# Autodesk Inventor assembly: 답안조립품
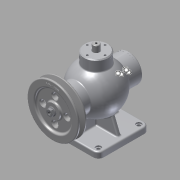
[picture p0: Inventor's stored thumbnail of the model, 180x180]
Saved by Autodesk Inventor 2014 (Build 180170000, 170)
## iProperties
Created: 2015-10
Part Number: 답안조립품
Document SubType Name: Assembly
Designer: youjin03
Author: youjin03
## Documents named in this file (19)
- C:\Users\youjin03\Desktop\451010V1015\답안조립품.iam
- C:\Users\youjin03\Desktop\451010V1015\본체.ipt
- C:\Users\youjin03\Desktop\451010V1015\뒤커버.ipt
- C:\Users\youjin03\Desktop\451010V1015\앞커버.ipt
- C:\Users\youjin03\Desktop\451010V1015\상부커버.ipt
- C:\Users\youjin03\Desktop\451010V1015\볼트 M4 x 16.ipt
- C:\Users\youjin03\Desktop\451010V1015\볼트 M 4 x 12.ipt
- C:\Users\youjin03\Desktop\451010V1015\오일실 15 30 7.ipt
- C:\Users\youjin03\Desktop\451010V1015\편심축.ipt
- C:\Users\youjin03\Desktop\451010V1015\베어링- 6202.ipt
- KS B 2023 - 6202 - 15 x 35 x 11 - 7.8.ipt
- C:\Users\youjin03\Desktop\451010V1015\부시.ipt
- C:\Users\youjin03\Desktop\451010V1015\키 4 x 4 x 12.ipt
- C:\Users\youjin03\Desktop\451010V1015\V-벨트풀리.ipt
- C:\Users\youjin03\Desktop\451010V1015\너트 M8.ipt
- C:\Users\youjin03\Desktop\451010V1015\슬라이드.ipt
- C:\Users\youjin03\Desktop\451010V1015\멈춤링- 35x1.6.ipt
- KS B 1336 - 35x1.6.ipt
- C:\Users\youjin03\Desktop\451010V1015\멈춤링- 15 x 1.ipt
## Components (16 placed, 5 different names)
1. KS B 2023 - 6202 - 15 x 35 x 11 - 7.8:1
2. KS B 2023 - 6202 - 15 x 35 x 11 - 7.8:2
3. V-벨트풀리:1
4. KS B 1336 - 35x1.6:1
5. ISO 4762 M4 x 16:1
6. ISO 4762 M4 x 16:3
7. ISO 4762 M4 x 16:4
8. ISO 4762 M4 x 16:5
9. ISO 4762 M4 x 16:2
10. ISO 4762 M4 x 16:6
11. ISO 4762 M4 x 16:7
12. ISO 4762 M4 x 16:8
13. KS B 1021 - 에 따름 ISO 1207 - 미터 A  M 4 x 12:1
14. KS B 1021 - 에 따름 ISO 1207 - 미터 A  M 4 x 12:2
15. KS B 1021 - 에 따름 ISO 1207 - 미터 A  M 4 x 12:3
16. KS B 1021 - 에 따름 ISO 1207 - 미터 A  M 4 x 12:4
